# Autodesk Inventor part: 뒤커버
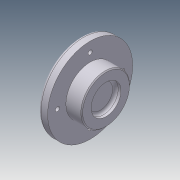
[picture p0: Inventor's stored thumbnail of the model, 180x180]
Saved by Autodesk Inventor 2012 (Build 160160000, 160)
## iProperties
Company: 한국ATC센터
Created: 2014-11
Part Number: 뒤커버
Document SubType Name: Modeling
Designer: KYOUNG IL JANG
Density: 2.71 g/cm^3
Material: 알루미늄-6061
Mass: 280.898 g
Surface Area: 198.677 cm^2
Volume: 103.653 cm^3
Author: KYOUNG IL JANG
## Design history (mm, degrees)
sketch "스케치1"
  geometry: L1 (-13.5, 0)-(13.5, 0); L2 (-13.5, 0)-(-13.5, 45.5); L3 (-13.5, 45.5)-(-3.5, 45.5); L4 (-3.5, 45.5)-(-3.5, 26); L5 (-3.5, 26)-(13.5, 26); L6 (13.5, 26)-(13.5, 0); 2 further points
  constraints: 12 end point, 3 parallel, 2 perpendicular, 1 coincident, 1 horizontal, 1 midpoint
  dimensions: "d0" = 27 distance of L1.start L1.end; "d1" = 91 diameter of L3 L1; "d2" = 52 diameter of L5 L1; "d3" = 10 distance of L2.end L3.end
revolve "회전1" sketch "스케치1" stored, may be unused: angle "d4" = 90 deg
sketch "스케치2"
  geometry: 2 further points
  constraints: 1 vertical alignment
  dimensions: "d14" = 35 distance of point (0, 0) point (0, 35)
hole "구멍2" sketch "스케치2" at (0, 35) diameter "d15" = 4.5; stored, may be unused: countersink angle "d19" = 90 deg, drill point angle "d21" = 118 deg; dims "d16" = 6, "d17" = 8, "d18" = 4.4, "d20" = 8
fillet "모깎기1" dims "d29" = 3
chamfer "모따기2" distance "d30" = 1; stored, may be unused: second distance "d31" = 2, angle "d32" = 30 deg
sketch "스케치3"
  geometry: L1 (-22.444, 6.652)-(-10, 14.967); L2 (-22.444, -6.652)-(-10, -14.967); L3 (10, -14.967)-(22.444, -6.652); L4 (22.444, 6.652)-(10, 14.967); A1 r 18 centre (0, 0) between (-18, 0) and (18, 0); A2 r 8 centre (18, 0) between (22.444, -6.652) and (22.444, 6.652); A3 r 8 centre (-18, 0) between (-22.444, 6.652) and (-22.444, -6.652); 1 further point
  constraints: 10 point on circle, 8 end point, 6 tangent, 3 centre point, 2 horizontal alignment, 2 parallel, 1 coincident, 1 equal radius
  dimensions: "d36" = 36 diameter of A1; "d37" = 16 diameter of A2
extrude "돌출1" join sketch "스케치3" distance "d38" = 7; taper "d39" = 0 deg
hole "구멍3" diameter "d43" = 32; stored, may be unused: countersink angle "d47" = 90 deg, drill point angle "d49" = 0 deg; dims "d41" = 10, "d42" = 10, "d44" = 6, "d45" = 4, "d46" = 2, "d48" = 6
fillet "모깎기2" dims "d40" = 3
node "솔리드1"
pattern_circular "원형 패턴2" dims angle "d34" = 360 deg
